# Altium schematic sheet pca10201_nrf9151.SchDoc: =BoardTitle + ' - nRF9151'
size A3; Organization: Nordic Semiconductor; DocumentNumber: 2; SheetNumber: 2; SheetTotal: 10; CompanyName: Nordic Semiconductor; DocumentSize: A3
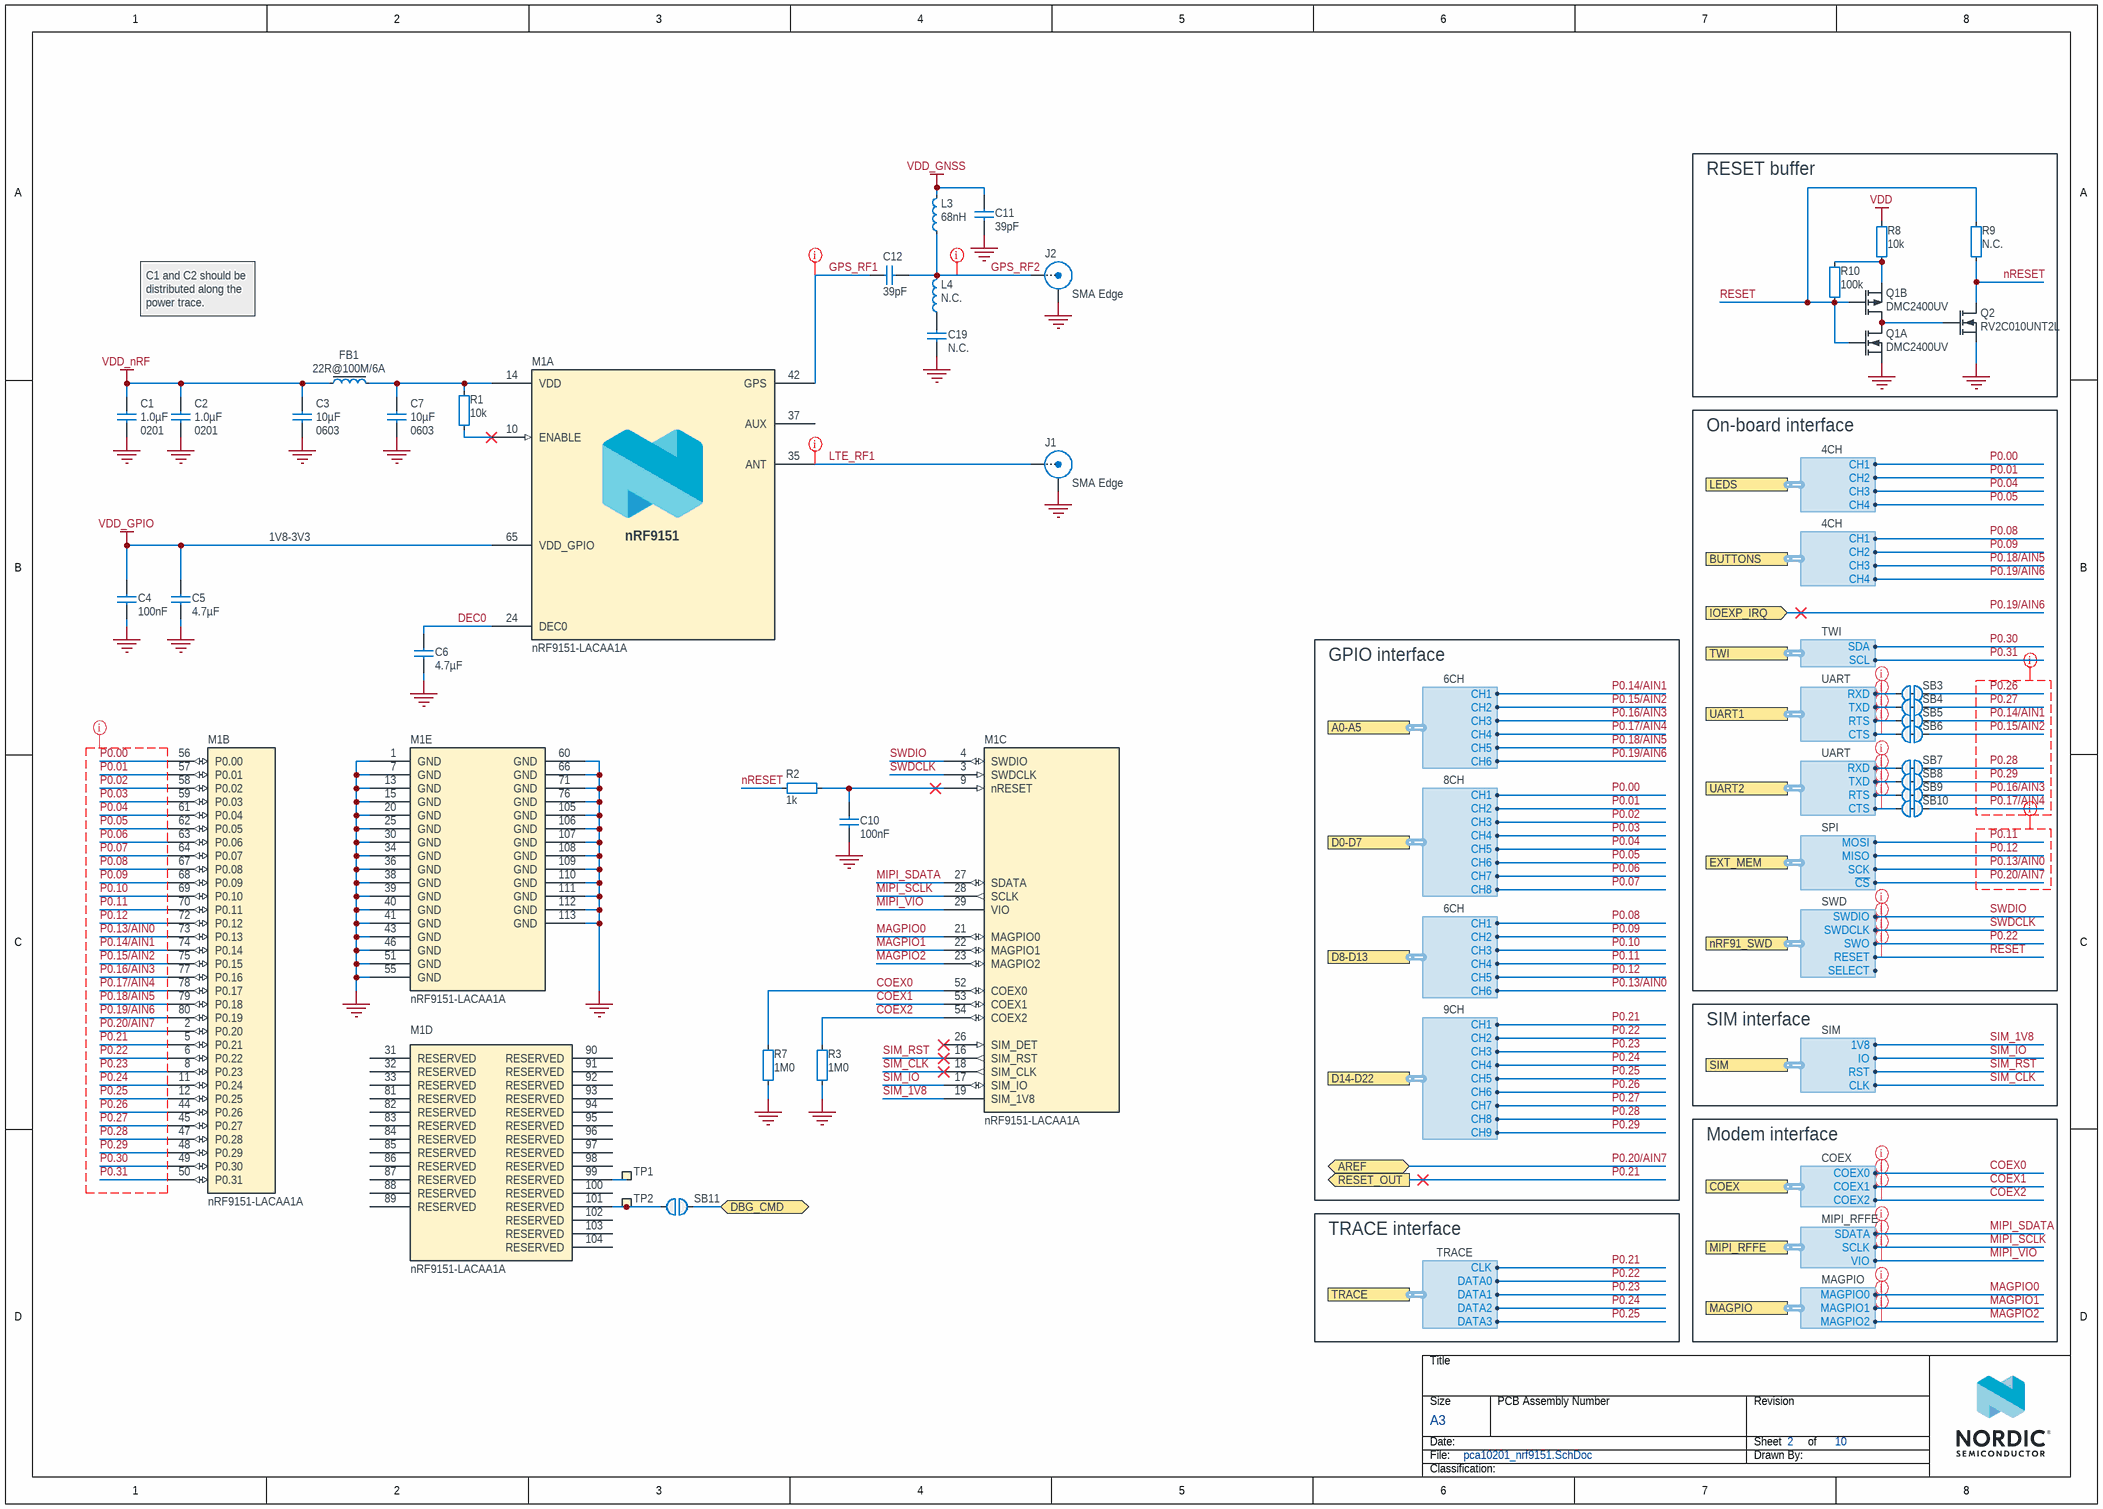
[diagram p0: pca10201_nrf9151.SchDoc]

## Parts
C1  1.0µF  Footprint Doc: 0201  [CAPC0603X03L_C]
C2  1.0µF  Footprint Doc: 0201  [CAPC0603X03L_C]
C3  10µF  Footprint Doc: 0603  [CAPC1608X06L]
C4  100nF  [CAPC0603X03L_C]
C5  4.7µF  [CAPC1005X04L]
C6  4.7µF  [CAPC1005X04L]
C7  10µF  Footprint Doc: 0603  [CAPC1608X06L]
C10  100nF  [CAPC0603X03L_C]
C11  39pF  [CAPC0603X03L_C]
C12  39pF  [CAPC0603X03L_C]
C19  N.C.  [CAPC0603X03L_C_NC]
FB1  22R@100M/6A  [INDC1608X06L]
J1  SMA Edge  [CONSMA024-G]
J2  SMA Edge  [CONSMA024-G]
L3  68nH  [INDC1005X04L_WW]
L4  N.C.  [INDC1005X04L_NC]
M1  nRF9151-LACAA1A  [LGA50P1210X1110X130-113N]  (parts A,B,C,D,E of 5)
Q1  DMC2400UV  [SOTFL50P162X60-6N]  (parts A,B of 2)
Q2  RV2C010UNT2L  [DFN65P100X40-3L]
R1  10k  [RESC0603X03L_C]
R2  1k  [RESC0603X03L_C]
R3  1M0  [RESC0603X03L_C]
R7  1M0  [RESC0603X03L_C]
R8  10k  [RESC0603X03L_C]
R9  N.C.  [RESC0603X03L_C_NC]
R10  100k  [RESC0603X03L_C]
SB3  Solderbridge  [Solderbridge_Shorted]  (value not drawn)  (net tie, no BOM)
SB4  Solderbridge  [Solderbridge_Shorted]  (value not drawn)  (net tie, no BOM)
SB5  Solderbridge  [Solderbridge_Shorted]  (value not drawn)  (net tie, no BOM)
SB6  Solderbridge  [Solderbridge_Shorted]  (value not drawn)  (net tie, no BOM)
SB7  Solderbridge  [Solderbridge_Shorted]  (value not drawn)  (net tie, no BOM)
SB8  Solderbridge  [Solderbridge_Shorted]  (value not drawn)  (net tie, no BOM)
SB9  Solderbridge  [Solderbridge_Shorted]  (value not drawn)  (net tie, no BOM)
SB10  Solderbridge  [Solderbridge_Shorted]  (value not drawn)  (net tie, no BOM)
SB11  Solderbridge  [Solderbridge]  (value not drawn)  (no BOM)
TP1  Ø1.0mm,SMD  [TP_SMD_D1.0mm]  (value not drawn)  (no BOM)
TP2  Ø1.0mm,SMD  [TP_SMD_D1.0mm]  (value not drawn)  (no BOM)

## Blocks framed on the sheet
RESET buffer: Q1 Q2 R8-R10
On-board interface: SB3-SB10

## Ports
A0-A5 (harness 6CH), AREF (bidir), BUTTONS (harness 4CH), COEX (harness COEX), D0-D7 (harness 8CH), D8-D13 (harness 6CH), D14-D22 (harness 9CH), DBG_CMD (bidir), EXT_MEM (harness SPI), IOEXP_IRQ (in), LEDS (harness 4CH), MAGPIO (harness MAGPIO), MIPI_RFFE (harness MIPI_RFFE), nRF91_SWD (harness SWD), RESET_OUT (out), SIM (harness SIM), TRACE (harness TRACE), TWI (harness TWI), UART1 (harness UART), UART2 (harness UART)

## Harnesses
COEX: COEX0, COEX2, COEX1
UART: RTS, CTS, RXD, TXD
SIM: CLK, IO, 1V8, RST
SWD: SWDIO, SWDCLK, SWO, RESET, SELECT
TWI: SCL, SDA
TRACE: CLK, DATA0, DATA1, DATA3, DATA2
SPI: SCK, ~{CS}, MOSI, MISO
MIPI_RFFE: SDATA, VIO, SCLK
MAGPIO: MAGPIO0, MAGPIO2, MAGPIO1
4CH: CH1, CH2, CH3, CH4
6CH: CH1, CH2, CH3, CH4, CH5, CH6
8CH: CH1, CH2, CH3, CH4, CH5, CH6, CH7, CH8
9CH: CH1, CH2, CH3, CH4, CH5, CH6, CH7, CH8, CH9

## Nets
GND: C1.2 C2.2 C3.2 C4.2 C5.2 C6.2 C7.2 C10.2 C11.1 C19.1 J1.2(Y) J2.2(Y) M1.1(GND) M1.7(GND) M1.13(GND) M1.15(GND) M1.20(GND) M1.25(GND) M1.30(GND) M1.34(GND) M1.36(GND) M1.38(GND) M1.39(GND) M1.40(GND) M1.41(GND) M1.43(GND) M1.46(GND) M1.51(GND) M1.55(GND) M1.60(GND) M1.66(GND) M1.71(GND) M1.76(GND) M1.105(GND) M1.106(GND) M1.107(GND) M1.108(GND) M1.109(GND) M1.110(GND) M1.111(GND) M1.112(GND) M1.113(GND) Q1.1(S1) Q2.2(S) R3.1 R7.1
VDD: R8.1
VDD_GNSS: C11.2 L3.1
VDD_GPIO: C4.1 C5.1 M1.65(VDD_GPIO)
VDD_nRF: C1.1 C2.1 C3.1 FB1.1
COEX0: M1.52(COEX0) R7.2 ; port COEX.COEX0
COEX1: M1.53(COEX1) ; port COEX.COEX1
COEX2: M1.54(COEX2) R3.2 ; port COEX.COEX2
DBG_CMD: SB11.1 ; port DBG_CMD
DEC0: C6.1 M1.24(DEC0)
GPS_RF1: C12.2 M1.42(GPS)
GPS_RF2: C12.1 J2.1(X) L3.2 L4.1
LTE_RF1: J1.1(X) M1.35(ANT)
MAGPIO0: M1.21(MAGPIO0) ; port MAGPIO.MAGPIO0
MAGPIO1: M1.22(MAGPIO1) ; port MAGPIO.MAGPIO1
MAGPIO2: M1.23(MAGPIO2) ; port MAGPIO.MAGPIO2
MIPI_SCLK: M1.28(SCLK) ; port MIPI_RFFE.SCLK
MIPI_SDATA: M1.27(SDATA) ; port MIPI_RFFE.SDATA
MIPI_VIO: M1.29(VIO) ; port MIPI_RFFE.VIO
nRESET: Q2.3(D) R2.1 R9.2
P0.00: M1.56(P0.00) ; port LEDS.CH1, port D0-D7.CH1
P0.01: M1.57(P0.01) ; port LEDS.CH2, port D0-D7.CH2
P0.02: M1.58(P0.02) ; port D0-D7.CH3
P0.03: M1.59(P0.03) ; port D0-D7.CH4
P0.04: M1.61(P0.04) ; port LEDS.CH3, port D0-D7.CH5
P0.05: M1.62(P0.05) ; port LEDS.CH4, port D0-D7.CH6
P0.06: M1.63(P0.06) ; port D0-D7.CH7
P0.07: M1.64(P0.07) ; port D0-D7.CH8
P0.08: M1.67(P0.08) ; port BUTTONS.CH1, port D8-D13.CH1
P0.09: M1.68(P0.09) ; port BUTTONS.CH2, port D8-D13.CH2
P0.10: M1.69(P0.10) ; port D8-D13.CH3
P0.11: M1.70(P0.11) ; port EXT_MEM.MOSI, port D8-D13.CH4
P0.12: M1.72(P0.12) ; port EXT_MEM.MISO, port D8-D13.CH5
P0.13/AIN0: M1.73(P0.13) ; port EXT_MEM.SCK, port D8-D13.CH6
P0.14/AIN1: M1.74(P0.14) SB5.1 ; port A0-A5.CH1
P0.15/AIN2: M1.75(P0.15) SB6.1 ; port A0-A5.CH2
P0.16/AIN3: M1.77(P0.16) SB9.1 ; port A0-A5.CH3
P0.17/AIN4: M1.78(P0.17) SB10.1 ; port A0-A5.CH4
P0.18/AIN5: M1.79(P0.18) ; port BUTTONS.CH3, port A0-A5.CH5
P0.19/AIN6: M1.80(P0.19) ; port IOEXP_IRQ, port BUTTONS.CH4, port A0-A5.CH6
P0.20/AIN7: M1.2(P0.20) ; port AREF, port EXT_MEM.~{CS}
P0.21: M1.5(P0.21) ; port RESET_OUT, port TRACE.CLK, port D14-D22.CH1
P0.22: M1.6(P0.22) ; port nRF91_SWD.SWO, port TRACE.DATA0, port D14-D22.CH2
P0.23: M1.8(P0.23) ; port TRACE.DATA1, port D14-D22.CH3
P0.24: M1.11(P0.24) ; port TRACE.DATA2, port D14-D22.CH4
P0.25: M1.12(P0.25) ; port TRACE.DATA3, port D14-D22.CH5
P0.26: M1.44(P0.26) SB3.1 ; port D14-D22.CH6
P0.27: M1.45(P0.27) SB4.1 ; port D14-D22.CH7
P0.28: M1.47(P0.28) SB7.1 ; port D14-D22.CH8
P0.29: M1.48(P0.29) SB8.1 ; port D14-D22.CH9
P0.30: M1.49(P0.30) ; port TWI.SDA
P0.31: M1.50(P0.31) ; port TWI.SCL
RESET: Q1.2(G1) Q1.5(G2) R9.1 R10.1 ; port nRF91_SWD.RESET
SIM_1V8: M1.19(SIM_1V8) ; port SIM.1V8
SIM_CLK: M1.18(SIM_CLK) ; port SIM.CLK
SIM_IO: M1.17(SIM_IO) ; port SIM.IO
SIM_RST: M1.16(SIM_RST) ; port SIM.RST
SWDCLK: M1.3(SWDCLK) ; port nRF91_SWD.SWDCLK
SWDIO: M1.4(SWDIO) ; port nRF91_SWD.SWDIO
NetC7_1: C7.1 FB1.2 M1.14(VDD) R1.1
NetC10_1: C10.1 M1.9(nRESET) R2.2
NetC19_2: C19.2 L4.2
NetM1_10: M1.10(ENABLE) R1.2
NetM1_99: M1.99(RESERVED) TP1.1
NetM1_101: M1.101(RESERVED) SB11.2 TP2.1
NetQ1_3: Q1.3(D2) Q1.6(D1) Q2.1(G)
NetQ1_4: Q1.4(S2) R8.2 R10.2
NetSB3_2: SB3.2 ; port UART1.RXD
NetSB4_2: SB4.2 ; port UART1.TXD
NetSB5_2: SB5.2 ; port UART1.RTS
NetSB6_2: SB6.2 ; port UART1.CTS
NetSB7_2: SB7.2 ; port UART2.RXD
NetSB8_2: SB8.2 ; port UART2.TXD
NetSB9_2: SB9.2 ; port UART2.RTS
NetSB10_2: SB10.2 ; port UART2.CTS

Not connected (* = marked no-connect by the designer): M1 26(SIM_DET)* 31(RESERVED) 32(RESERVED) 33(RESERVED) 37(AUX) 81(RESERVED) 82(RESERVED) 83(RESERVED) 84(RESERVED) 85(RESERVED) 86(RESERVED) 87(RESERVED) 88(RESERVED) 89(RESERVED) 90(RESERVED) 91(RESERVED) 92(RESERVED) 93(RESERVED) 94(RESERVED) 95(RESERVED) 96(RESERVED) 97(RESERVED) 98(RESERVED) 100(RESERVED) 102(RESERVED) 103(RESERVED) 104(RESERVED)

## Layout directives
net class SWD: P0.22, RESET, SWDCLK, SWDIO
net class COEX: COEX0, COEX1, COEX2, MAGPIO0, MAGPIO1, MAGPIO2, MIPI_SCLK, MIPI_SDATA, MIPI_VIO
net class GPIO: NetSB3_2, NetSB4_2, NetSB5_2, NetSB6_2, NetSB7_2, NetSB8_2, NetSB9_2, NetSB10_2, P0.00, P0.01, P0.02, P0.03, P0.04, P0.05, P0.06, P0.07, P0.08, P0.09, P0.10, P0.11, P0.12, P0.13/AIN0, P0.14/AIN1, P0.15/AIN2, P0.16/AIN3, P0.17/AIN4, P0.18/AIN5, P0.19/AIN6, P0.20/AIN7, P0.21, P0.22, P0.23, P0.24, P0.25, P0.26, P0.27, P0.28, P0.29, P0.30, P0.31
net class RF: GPS_RF1, GPS_RF2, LTE_RF1
net class nRF9151_UART: P0.14/AIN1, P0.15/AIN2, P0.16/AIN3, P0.17/AIN4, P0.26, P0.27, P0.28, P0.29
net class EXT_MEM: P0.11, P0.12, P0.13/AIN0, P0.20/AIN7

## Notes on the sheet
- C1 and C2 should be distributed along the power trace.
- 1V8-3V3
- GPIO interface
- SIM interface
- Modem interface
- TRACE interface

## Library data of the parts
C1 C2 = C0201-1µ0-10V-X5R-GRM033R61A105ME15: Capacitor, X5R, ±20%, 10V; Manufacturer: Murata; Part number NEMS: 100200545; Artikkelnr Noca: N.A.; Pad Count: 2; Component Status: Active
C3 C7 = C0603-10µ-10V-X6S-GRM188C81A106MA73: Capacitor, Ceramic, 10µF 10V X6S 0603,±20%; Manufacturer: Murata; Part number NEMS: 100200520; Component Status: Active; Pad Count: 2; Artikkelnr Noca: N.A.
C4 C10 = C0201-100n: Capacitor, X5R, ±10%, 100nF, 16V; Manufacturer: N.A.; Part number IPS: 00000001248, 00000002505; Part number Norautron: 262071862; Part number NEMS: 100200078; Pad Count: 2; Component Status: Active
C5 C6 = C0402-4µ7-10V-X5R: Capacitor, X5R, 10V; Manufacturer: Murata; Manufacturer Part Number: GRM155R61A475MEAAD; Part number NEMS: 100200415; Artikkelnr Noca: N.A.; Pad Count: 2; Component Status: Active
C11 C12 = C0201-39p: Capacitor, NP0, ±1%, 25V; Manufacturer: Murata; Manufacturer Part Number: GRM0335C1E390FA01D; Part number IPS: 00000001668; Part number NEMS: 100200039; Artikkelnr Noca: N.A.; Pad Count: 2; Component Status: Active
C19 = C0201-N.C.: Not mounted; Manufacturer: N.A.; Part number NEMS: 100200001; Assembly: Not mounted; Note: Chip Cap; Pad Count: 2; Component Status: Active
FB1 = FB0603-22R@100MHz-6000mA: Ferrite Bead, 22 Ohm @ 100MHz, 6000mA, 8 mOhm Max; Manufacturer: Murata; Manufacturer Part Number: BLM18SD220SN1D; Part number NEMS: 100300492; Component Status: Active; Pad Count: 2; Note: Chip EMIFIL Inductor Type Chip Ferrite Bead; Artikkelnr Noca: N.A.
J1 J2 = SMA-Edge-C02AJ3F64B-1: SMA Jack, Female, 50 Ohm, Board Edge, Cutout, SMT; Manufacturer: Wellshow Technology; Part number NEMS: 100500896; Component Status: Active; Pad Count: 2; Note: N.A.; System: Connector
L3 = L0402-68n-Wirewound-Murata: Inductor, 140mA, ±2%, 1960mΩ, Q=20; Manufacturer: Murata; Manufacturer Part Number: LQW15AN68NG00; Part number IPS: 00000002494; Part number NEMS: 100300389; Note: -55°C ~ 125°C; Artikkelnr Noca: N.A.; Pad Count: 2; Component Status: Active
L4 = L0402-N.C.: Not mounted; Manufacturer: N.A.; Part number NEMS: 100300037; Assembly: Not mounted; Pad Count: 2; Component Status: Active
M1 = nRF9151-LACAA1A: Low power System-in-Package with integrated LTE-M/NB-IoT modem and GPS; Manufacturer: Nordic Semiconductor; Part number NEMS: 102000407; Component Status: Active; Pad Count: 113; Note: N.A.
Q1 = DMC2400UV: Dual N & P Ch MOFET, 1.03A/0.7A, 480mOhm, 450mW; Manufacturer: Diodes Incorporated; Part number IPS: 00000007803; Part number NEMS: 101300117; Note: Dual N & P Channel Digital FET; Artikkelnr Noca: N.A.; Pad Count: 6; Component Status: Active
Q2 = RV2C010UNT2L: N-Channel MOSFET, 20V, 1A, 470mOhm, 400mW, -55°C ~ 150°C; Manufacturer: Rohm Semiconductor; Part number IPS: 00000009976; Part number Norautron: 26320026; Part number NEMS: 101300132; Note: N.A.; Artikkelnr Noca: 35010020; Pad Count: 3; Component Status: Active
R1 R8 = R0201-10k: Resistor, ±1%, 0.05W; Manufacturer: N.A.; Part number IPS: 00000001255; Part number Norautron: 26107101; Part number NEMS: 100100065; Note: Chip Res 1%; Pad Count: 2; Component Status: Active
R2 = R0201-1k0: Resistor, ±1%, 0.05W; Manufacturer: N.A.; Part number IPS: 00000005786; Part number NEMS: 100100043; Note: Chip Res 1%; Pad Count: 2; Component Status: Active
R3 R7 = R0201-1M0: Resistor, ±1%, 0.05W; Manufacturer: N.A.; Part number IPS: 00000001418; Part number Norautron: 26107108; Part number NEMS: 100100093; Note: Chip Res 1%; Pad Count: 2; Component Status: Active
R9 = R0201-N.C.: Not mounted; Manufacturer: N.A.; Part number NEMS: 100100107; Note: Chip Res; Assembly: Not mounted; Pad Count: 2; Component Status: Active
R10 = R0201-100k: Resistor, ±1%, 0.05W; Manufacturer: N.A.; Part number IPS: 00000001419; Part number Norautron: 26108487; Part number NEMS: 100100080; Note: Chip Res 1%; Pad Count: 2; Component Status: Active
SB3-SB10 = Solderbridge Shorted: Shorted Solderbridge; Manufacturer: N.A.; Part number NEMS: 100500459; Pad Count: 2; Component Status: Active; System: Connector
SB11 = Solderbridge: Manufacturer: N.A.; Part number NEMS: 100500458; Pad Count: 2; Component Status: Active; System: Connector
TP1 TP2 = TP_SMD_Ø1.0MM: 1.0mm circular SMD testpad; Manufacturer: Nordic Semiconductor; Manufacturer Part Number: N.A.; Part number NEMS: 100500475; Pad Count: 1; Component Status: Active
